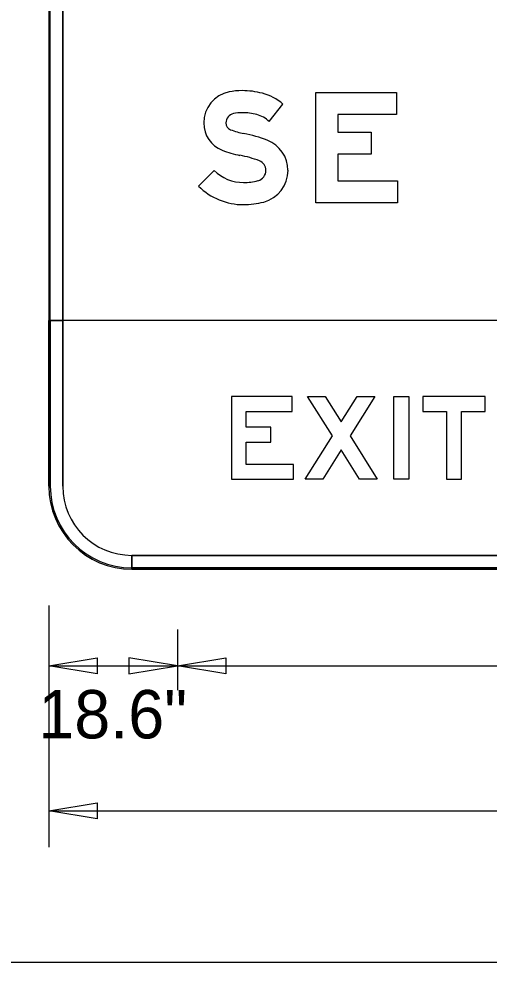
# Model space of a CAD drawing. Extents: x 2149934 to 2150188, y 145114 to 145238.
# Drawn here: x 2150089.92 to 2150095.59, y 145143.48 to 145154.85 of the extents above; entities that cross this region are included whole.
import ezdxf

# ---------------------------------------------------------------- set-up
doc = ezdxf.new("R2010")
doc.units = 0
for name, color, linetype in [('GSBWFILL', 7, 'Continuous'), ('GSCOLORFILL', 7, 'Continuous'), ('GSDIMS', 7, 'Continuous'), ('GSOUTLINE', 7, 'Continuous'), ('Level 1', 7, 'Continuous')]:
    doc.layers.add(name, color=color, linetype=linetype)

msp = doc.modelspace()

# ---------------------------------------------------------------- linework, layer by layer
at = {"layer": 'GSBWFILL'}
for p, q in [((2150090.279, 145163.216), (2150090.279, 145149.216)), ((2150090.445, 145149.216), (2150090.445, 145163.216)), ((2150090.279, 145149.216), (2150090.279, 145151.217)), ((2150090.279, 145151.217), (2150090.445, 145151.217)), ((2150105.779, 145151.217), (2150090.279, 145151.217)), ((2150090.279, 145151.217), (2150090.279, 145149.216)), ((2150090.445, 145151.217), (2150090.445, 145151.05)), ((2150090.445, 145151.05), (2150090.445, 145149.216)), ((2150091.279, 145148.216), (2150091.279, 145148.383)), ((2150091.279, 145148.383), (2150104.779, 145148.383)), ((2150104.779, 145148.383), (2150091.28, 145148.383)), ((2150091.28, 145148.383), (2150091.28, 145148.216)), ((2150104.779, 145148.216), (2150091.279, 145148.216)), ((2150091.279, 145148.216), (2150104.779, 145148.216)), ((2150091.28, 145148.216), (2150104.779, 145148.216))]:
    msp.add_line(p, q, dxfattribs=at)
for points in [[(2150094.469, 145153.967), (2150094.469, 145153.7), (2150093.763, 145153.7), (2150093.763, 145153.487), (2150094.163, 145153.487), (2150094.163, 145153.22), (2150093.763, 145153.22), (2150093.763, 145152.9), (2150094.483, 145152.9), (2150094.483, 145152.634), (2150093.496, 145152.634), (2150093.496, 145153.967)], [(2150093.229, 145149.48), (2150092.659, 145149.48), (2150092.659, 145149.749), (2150092.954, 145149.749), (2150092.954, 145149.929), (2150092.659, 145149.929), (2150092.659, 145150.12), (2150093.214, 145150.12), (2150093.214, 145150.3), (2150092.479, 145150.3), (2150092.479, 145149.3), (2150093.229, 145149.3)], [(2150094.026, 145149.3), (2150093.804, 145149.655), (2150093.581, 145149.3), (2150093.369, 145149.3), (2150093.698, 145149.824), (2150093.399, 145150.3), (2150093.611, 145150.3), (2150093.804, 145149.993), (2150093.996, 145150.3), (2150094.209, 145150.3), (2150093.91, 145149.824), (2150094.239, 145149.3)], [(2150094.439, 145149.3), (2150094.439, 145150.3), (2150094.619, 145150.3), (2150094.619, 145149.3)], [(2150094.789, 145150.12), (2150095.074, 145150.12), (2150095.074, 145149.3), (2150095.254, 145149.3), (2150095.254, 145150.12), (2150095.539, 145150.12), (2150095.539, 145150.3), (2150094.789, 145150.3)]]:
    msp.add_lwpolyline(points, close=True, dxfattribs=at)
for points in [[(2150092.936, 145153.615), (2150093.101, 145153.826)], [(2150092.271, 145153.026), (2150092.083, 145152.836)]]:
    msp.add_lwpolyline(points, dxfattribs=at)
for radius in [1, 1, 1, 0.833, 0.833]:
    msp.add_arc((2150091.279, 145149.216), radius, 180, 270, dxfattribs=at)
for centre, major_axis, start_param, end_param in [((2150092.609, 145153.203), (0, 0.785), 0, 0.202758), ((2150092.609, 145153.025), (0, 0.963), 6.026234, 6.283185), ((2150092.528, 145153.598), (0, 0.382), 0.202758, 1.570796), ((2150092.699, 145153.365), (0, 0.611), 5.565152, 6.026234), ((2150092.528, 145153.598), (0, 0.115), 0.202758, 1.570796), ((2150092.609, 145153.203), (0, 0.519), 0, 0.202758), ((2150092.609, 145153.025), (0, 0.697), 6.026234, 6.283185), ((2150092.699, 145153.365), (0, 0.345), 5.523837, 6.026234), ((2150092.5, 145153.598), (0, 0.354), 1.570796, 2.761249), ((2150092.5, 145153.598), (0, 0.0872), 1.570796, 2.761249), ((2150092.791, 145154.325), (0, 0.87), 2.761249, 2.95744), ((2150092.334, 145151.874), (0, 1.623), 5.918637, 6.099033), ((2150092.774, 145153.027), (0, 0.388), 4.712389, 5.918637), ((2150092.791, 145154.325), (0, 1.137), 2.761249, 2.95744), ((2150092.334, 145151.874), (0, 1.357), 5.918637, 6.099033), ((2150092.774, 145153.027), (0, 0.122), 4.712389, 5.918637), ((2150092.626, 145153.384), (0, 0.504), 2.360607, 3.141593), ((2150092.767, 145153.027), (0, 0.129), 3.401517, 4.712389), ((2150092.767, 145153.027), (0, 0.396), 3.401517, 4.712389), ((2150092.626, 145153.558), (0, 0.678), 3.141593, 3.401517), ((2150092.626, 145153.384), (0, 0.771), 2.360607, 3.141593), ((2150092.626, 145153.558), (0, 0.945), 3.141593, 3.401517)]:
    msp.add_ellipse(centre, major_axis=major_axis, ratio=0.999994, start_param=start_param, end_param=end_param, dxfattribs=at)
at = {"layer": 'GSCOLORFILL'}
for p, q in [((2150090.279, 145163.216), (2150090.279, 145149.216)), ((2150090.279, 145163.216), (2150090.279, 145149.216)), ((2150090.279, 145163.216), (2150090.279, 145149.216)), ((2150090.295, 145149.216), (2150090.295, 145163.216)), ((2150090.445, 145149.216), (2150090.445, 145163.216)), ((2150105.779, 145151.217), (2150090.279, 145151.217)), ((2150090.279, 145151.217), (2150090.279, 145149.216)), ((2150090.279, 145149.216), (2150090.279, 145151.217)), ((2150090.279, 145151.217), (2150090.445, 145151.217)), ((2150090.279, 145149.216), (2150090.279, 145151.217)), ((2150090.279, 145151.217), (2150090.295, 145151.217)), ((2150090.295, 145151.217), (2150090.295, 145151.2)), ((2150090.295, 145151.2), (2150090.295, 145149.216)), ((2150090.445, 145151.217), (2150090.445, 145151.05)), ((2150090.445, 145151.05), (2150090.445, 145149.216)), ((2150091.279, 145148.216), (2150091.279, 145148.383)), ((2150091.279, 145148.383), (2150104.779, 145148.383)), ((2150104.779, 145148.383), (2150091.28, 145148.383)), ((2150091.28, 145148.383), (2150091.28, 145148.216)), ((2150091.279, 145148.216), (2150091.279, 145148.233)), ((2150104.779, 145148.233), (2150091.279, 145148.233)), ((2150091.279, 145148.233), (2150091.279, 145148.216)), ((2150091.279, 145148.233), (2150104.779, 145148.233)), ((2150091.279, 145148.216), (2150104.779, 145148.216)), ((2150091.279, 145148.216), (2150104.779, 145148.216)), ((2150091.279, 145148.216), (2150104.779, 145148.216)), ((2150104.779, 145148.216), (2150091.279, 145148.216)), ((2150104.779, 145148.216), (2150091.279, 145148.216)), ((2150091.28, 145148.216), (2150104.779, 145148.216))]:
    msp.add_line(p, q, dxfattribs=at)
for points in [[(2150094.469, 145153.967), (2150094.469, 145153.7), (2150093.763, 145153.7), (2150093.763, 145153.487), (2150094.163, 145153.487), (2150094.163, 145153.22), (2150093.763, 145153.22), (2150093.763, 145152.9), (2150094.483, 145152.9), (2150094.483, 145152.634), (2150093.496, 145152.634), (2150093.496, 145153.967)], [(2150093.229, 145149.48), (2150092.659, 145149.48), (2150092.659, 145149.749), (2150092.954, 145149.749), (2150092.954, 145149.929), (2150092.659, 145149.929), (2150092.659, 145150.12), (2150093.214, 145150.12), (2150093.214, 145150.3), (2150092.479, 145150.3), (2150092.479, 145149.3), (2150093.229, 145149.3)], [(2150094.026, 145149.3), (2150093.804, 145149.655), (2150093.581, 145149.3), (2150093.369, 145149.3), (2150093.698, 145149.824), (2150093.399, 145150.3), (2150093.611, 145150.3), (2150093.804, 145149.993), (2150093.996, 145150.3), (2150094.209, 145150.3), (2150093.91, 145149.824), (2150094.239, 145149.3)], [(2150094.439, 145149.3), (2150094.439, 145150.3), (2150094.619, 145150.3), (2150094.619, 145149.3)], [(2150094.789, 145150.12), (2150095.074, 145150.12), (2150095.074, 145149.3), (2150095.254, 145149.3), (2150095.254, 145150.12), (2150095.539, 145150.12), (2150095.539, 145150.3), (2150094.789, 145150.3)]]:
    msp.add_lwpolyline(points, close=True, dxfattribs=at)
for points in [[(2150092.936, 145153.615), (2150093.101, 145153.826)], [(2150092.271, 145153.026), (2150092.083, 145152.836)]]:
    msp.add_lwpolyline(points, dxfattribs=at)
for radius in [1, 1, 1, 1, 1, 1, 0.983, 0.983, 0.833, 0.833]:
    msp.add_arc((2150091.279, 145149.216), radius, 180, 270, dxfattribs=at)
for centre, major_axis, start_param, end_param in [((2150092.609, 145153.203), (0, 0.785), 0, 0.202758), ((2150092.609, 145153.025), (0, 0.963), 6.026234, 6.283185), ((2150092.528, 145153.598), (0, 0.382), 0.202758, 1.570796), ((2150092.699, 145153.365), (0, 0.611), 5.565152, 6.026234), ((2150092.528, 145153.598), (0, 0.115), 0.202758, 1.570796), ((2150092.609, 145153.203), (0, 0.519), 0, 0.202758), ((2150092.609, 145153.025), (0, 0.697), 6.026234, 6.283185), ((2150092.699, 145153.365), (0, 0.345), 5.523837, 6.026234), ((2150092.5, 145153.598), (0, 0.354), 1.570796, 2.761249), ((2150092.5, 145153.598), (0, 0.0872), 1.570796, 2.761249), ((2150092.791, 145154.325), (0, 0.87), 2.761249, 2.95744), ((2150092.334, 145151.874), (0, 1.623), 5.918637, 6.099033), ((2150092.774, 145153.027), (0, 0.388), 4.712389, 5.918637), ((2150092.791, 145154.325), (0, 1.137), 2.761249, 2.95744), ((2150092.334, 145151.874), (0, 1.357), 5.918637, 6.099033), ((2150092.774, 145153.027), (0, 0.122), 4.712389, 5.918637), ((2150092.626, 145153.384), (0, 0.504), 2.360607, 3.141593), ((2150092.767, 145153.027), (0, 0.129), 3.401517, 4.712389), ((2150092.767, 145153.027), (0, 0.396), 3.401517, 4.712389), ((2150092.626, 145153.558), (0, 0.678), 3.141593, 3.401517), ((2150092.626, 145153.384), (0, 0.771), 2.360607, 3.141593), ((2150092.626, 145153.558), (0, 0.945), 3.141593, 3.401517)]:
    msp.add_ellipse(centre, major_axis=major_axis, ratio=0.999994, start_param=start_param, end_param=end_param, dxfattribs=at)
at = {"layer": 'GSDIMS'}
for p, q in [((2150090.279, 145147.779), (2150090.279, 145144.862)), ((2150090.279, 145147.487), (2150090.279, 145146.758)), ((2150091.828, 145147.487), (2150091.828, 145146.758)), ((2150091.828, 145147.487), (2150091.828, 145146.758)), ((2150090.279, 145147.05), (2150091.828, 145147.05)), ((2150091.828, 145147.05), (2150104.229, 145147.05)), ((2150090.279, 145145.737), (2150090.279, 145145.008)), ((2150090.279, 145145.3), (2150105.779, 145145.3))]:
    msp.add_line(p, q, dxfattribs=at)
for points in [[(2150090.279, 145147.05), (2150090.862, 145147.147), (2150090.862, 145146.953)], [(2150091.828, 145147.05), (2150091.244, 145147.147), (2150091.244, 145146.953)], [(2150091.828, 145147.05), (2150092.411, 145147.147), (2150092.411, 145146.953)], [(2150090.279, 145145.3), (2150090.862, 145145.397), (2150090.862, 145145.203)]]:
    msp.add_lwpolyline(points, close=True, dxfattribs=at)
at = {"layer": 'GSOUTLINE'}
for p, q in [((2150090.279, 145163.216), (2150090.279, 145149.216)), ((2150090.445, 145163.216), (2150090.445, 145149.216)), ((2150090.279, 145149.216), (2150090.279, 145151.217)), ((2150090.279, 145151.217), (2150090.445, 145151.217)), ((2150105.779, 145151.217), (2150090.279, 145151.217)), ((2150090.279, 145151.217), (2150090.279, 145149.216)), ((2150090.445, 145151.217), (2150090.445, 145151.05)), ((2150090.445, 145151.05), (2150090.445, 145149.216)), ((2150091.279, 145148.383), (2150104.779, 145148.383)), ((2150091.279, 145148.383), (2150104.779, 145148.383)), ((2150091.279, 145148.216), (2150104.779, 145148.216)), ((2150104.779, 145148.216), (2150091.279, 145148.216)), ((2150091.279, 145148.216), (2150104.779, 145148.216))]:
    msp.add_line(p, q, dxfattribs=at)
for points in [[(2150094.469, 145153.967), (2150094.469, 145153.7), (2150093.763, 145153.7), (2150093.763, 145153.487), (2150094.163, 145153.487), (2150094.163, 145153.22), (2150093.763, 145153.22), (2150093.763, 145152.9), (2150094.483, 145152.9), (2150094.483, 145152.634), (2150093.496, 145152.634), (2150093.496, 145153.967)], [(2150093.229, 145149.48), (2150092.659, 145149.48), (2150092.659, 145149.749), (2150092.954, 145149.749), (2150092.954, 145149.929), (2150092.659, 145149.929), (2150092.659, 145150.12), (2150093.214, 145150.12), (2150093.214, 145150.3), (2150092.479, 145150.3), (2150092.479, 145149.3), (2150093.229, 145149.3)], [(2150094.026, 145149.3), (2150093.804, 145149.655), (2150093.581, 145149.3), (2150093.369, 145149.3), (2150093.698, 145149.824), (2150093.399, 145150.3), (2150093.611, 145150.3), (2150093.804, 145149.993), (2150093.996, 145150.3), (2150094.209, 145150.3), (2150093.91, 145149.824), (2150094.239, 145149.3)], [(2150094.439, 145149.3), (2150094.439, 145150.3), (2150094.619, 145150.3), (2150094.619, 145149.3)], [(2150094.789, 145150.12), (2150095.074, 145150.12), (2150095.074, 145149.3), (2150095.254, 145149.3), (2150095.254, 145150.12), (2150095.539, 145150.12), (2150095.539, 145150.3), (2150094.789, 145150.3)]]:
    msp.add_lwpolyline(points, close=True, dxfattribs=at)
for points in [[(2150092.936, 145153.615), (2150093.101, 145153.826)], [(2150092.271, 145153.026), (2150092.083, 145152.836)]]:
    msp.add_lwpolyline(points, dxfattribs=at)
for radius in [1, 1, 1, 0.833, 0.833]:
    msp.add_arc((2150091.279, 145149.216), radius, 180, 270, dxfattribs=at)
for centre, major_axis, start_param, end_param in [((2150092.609, 145153.203), (0, 0.785), 0, 0.202758), ((2150092.609, 145153.025), (0, 0.963), 6.026234, 6.283185), ((2150092.528, 145153.598), (0, 0.382), 0.202758, 1.570796), ((2150092.699, 145153.365), (0, 0.611), 5.565152, 6.026234), ((2150092.528, 145153.598), (0, 0.115), 0.202758, 1.570796), ((2150092.609, 145153.203), (0, 0.519), 0, 0.202758), ((2150092.609, 145153.025), (0, 0.697), 6.026234, 6.283185), ((2150092.699, 145153.365), (0, 0.345), 5.523837, 6.026234), ((2150092.5, 145153.598), (0, 0.354), 1.570796, 2.761249), ((2150092.5, 145153.598), (0, 0.0872), 1.570796, 2.761249), ((2150092.791, 145154.325), (0, 0.87), 2.761249, 2.95744), ((2150092.334, 145151.874), (0, 1.623), 5.918637, 6.099033), ((2150092.774, 145153.027), (0, 0.388), 4.712389, 5.918637), ((2150092.791, 145154.325), (0, 1.137), 2.761249, 2.95744), ((2150092.334, 145151.874), (0, 1.357), 5.918637, 6.099033), ((2150092.774, 145153.027), (0, 0.122), 4.712389, 5.918637), ((2150092.626, 145153.384), (0, 0.504), 2.360607, 3.141593), ((2150092.767, 145153.027), (0, 0.129), 3.401517, 4.712389), ((2150092.767, 145153.027), (0, 0.396), 3.401517, 4.712389), ((2150092.626, 145153.558), (0, 0.678), 3.141593, 3.401517), ((2150092.626, 145153.384), (0, 0.771), 2.360607, 3.141593), ((2150092.626, 145153.558), (0, 0.945), 3.141593, 3.401517)]:
    msp.add_ellipse(centre, major_axis=major_axis, ratio=0.999994, start_param=start_param, end_param=end_param, dxfattribs=at)
at = {"layer": 'Level 1'}
msp.add_line((2150076.316, 145143.476), (2150121.342, 145143.476), dxfattribs=at)

# ---------------------------------------------------------------- texts
at = {"layer": 'GSDIMS'}
msp.add_text('18.6"', height=0.5833, dxfattribs=at).set_placement((2150090.151, 145146.175))

doc.saveas('drawing.dxf')
